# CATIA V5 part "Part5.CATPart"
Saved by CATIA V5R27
Part number: Part5
Bounding box of the stored display mesh (mm): x -10.067 to 10.067, y -51 to 14, z 4.065 to 25.935
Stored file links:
  E:\university\my-thesis\My Thesis Publication\Final-Updata\CAD\Part5.CATPart
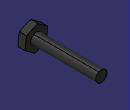
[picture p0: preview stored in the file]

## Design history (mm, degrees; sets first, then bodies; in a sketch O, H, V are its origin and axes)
Set1
  Sketch1 on yz-plane, origin (0, 0, 0), H (0, 1, 0), V (0, 0, 1)
    line L1 (14, 20) -> (-44, 20)
    line L2 (-44, 20) -> (-44, 26)
    line L3 (-44, 26) -> (-50, 26)
    line L4 (-50, 26) -> (-51, 23.5)
    line L5 (-51, 23.5) -> (-51, 15)
    line L6 (-51, 15) -> (14, 15)
    line L7 (14, 15) -> (14, 20)
    reference intersected line E1 through (0, 0) direction (0, 1) from zx-plane
    point P9 (3, 9)
    length L6 = 65
    distance L2 L5 = 7
    distance L3 L6 = 11
    length L5 = 8.5
    length L7 = 5
    length L3 = 6
    distance L7 E1 = 14
    distance L6 P9 = 6
    horizontal: L1 H, L3 H, L6 H
    vertical: L2 V, L5 V, L7 V
  DatumCurve1
  Sketch2 on face of Shaft1 from Sketch1.L5, origin (0, -51, 0), H (1, 0, 0), V (0, 0, 1)
    point P1 (0, 15)
    point P2 (3.8402, 23.718)
    construction circle A1 centre (0, 15) radius 11
    construction circle A2 centre (0, 15) radius 9.5263
    point P3 (8.8735, 21.5009)
    point P4 (-1.1932, 25.9351)
    point P5 (-10.0667, 19.4342)
    point P6 (-8.8735, 8.4991)
    point P7 (1.1932, 4.0649)
    point P8 (10.0667, 10.5658)
    line L1 (8.8735, 21.5009) -> (-1.1932, 25.9351)
    line L2 (-1.1932, 25.9351) -> (-10.0667, 19.4342)
    line L3 (-10.0667, 19.4342) -> (-8.8735, 8.4991)
    line L4 (-8.8735, 8.4991) -> (1.1932, 4.0649)
    line L5 (1.1932, 4.0649) -> (10.0667, 10.5658)
    line L6 (10.0667, 10.5658) -> (8.8735, 21.5009)
    construction line L7 (0, 15) -> (3.8402, 23.718)
    reference projected circle E1 centre (0, 15) radius 11 from edge [face of Shaft1 from Sketch1.L4 | face of Shaft1 from Sketch1.L3]
    reference projected circle E2 centre (0, 15) radius 11 from edge [face of Shaft1 from Sketch1.L4 | face of Shaft1 from Sketch1.L3]
    coincidence: A1 P3, A1 P4, A1 P5, A1 P6, A1 P7, A1 P8, P1 V, P4 E2
    tangency: A2 L1, A2 L2, A2 L3, A2 L4, A2 L5, A2 L6
    midpoint: P2 L1
    concentricity: P1 E1
Body1 (main body)
  Shaft1: profile Sketch1, axis Sketch1.L6, angle 360
  Pocket1: profile Sketch2, direction (0, 1, 0), up to face of Shaft1 from Sketch1.L2, outer side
